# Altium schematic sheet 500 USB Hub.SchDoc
size A3; Organization: Toradex Solutions Inc.; Address1: 6415 Northwest Drive; Address2: Mississauga, ON, L4V 1X1; Address3: Canada
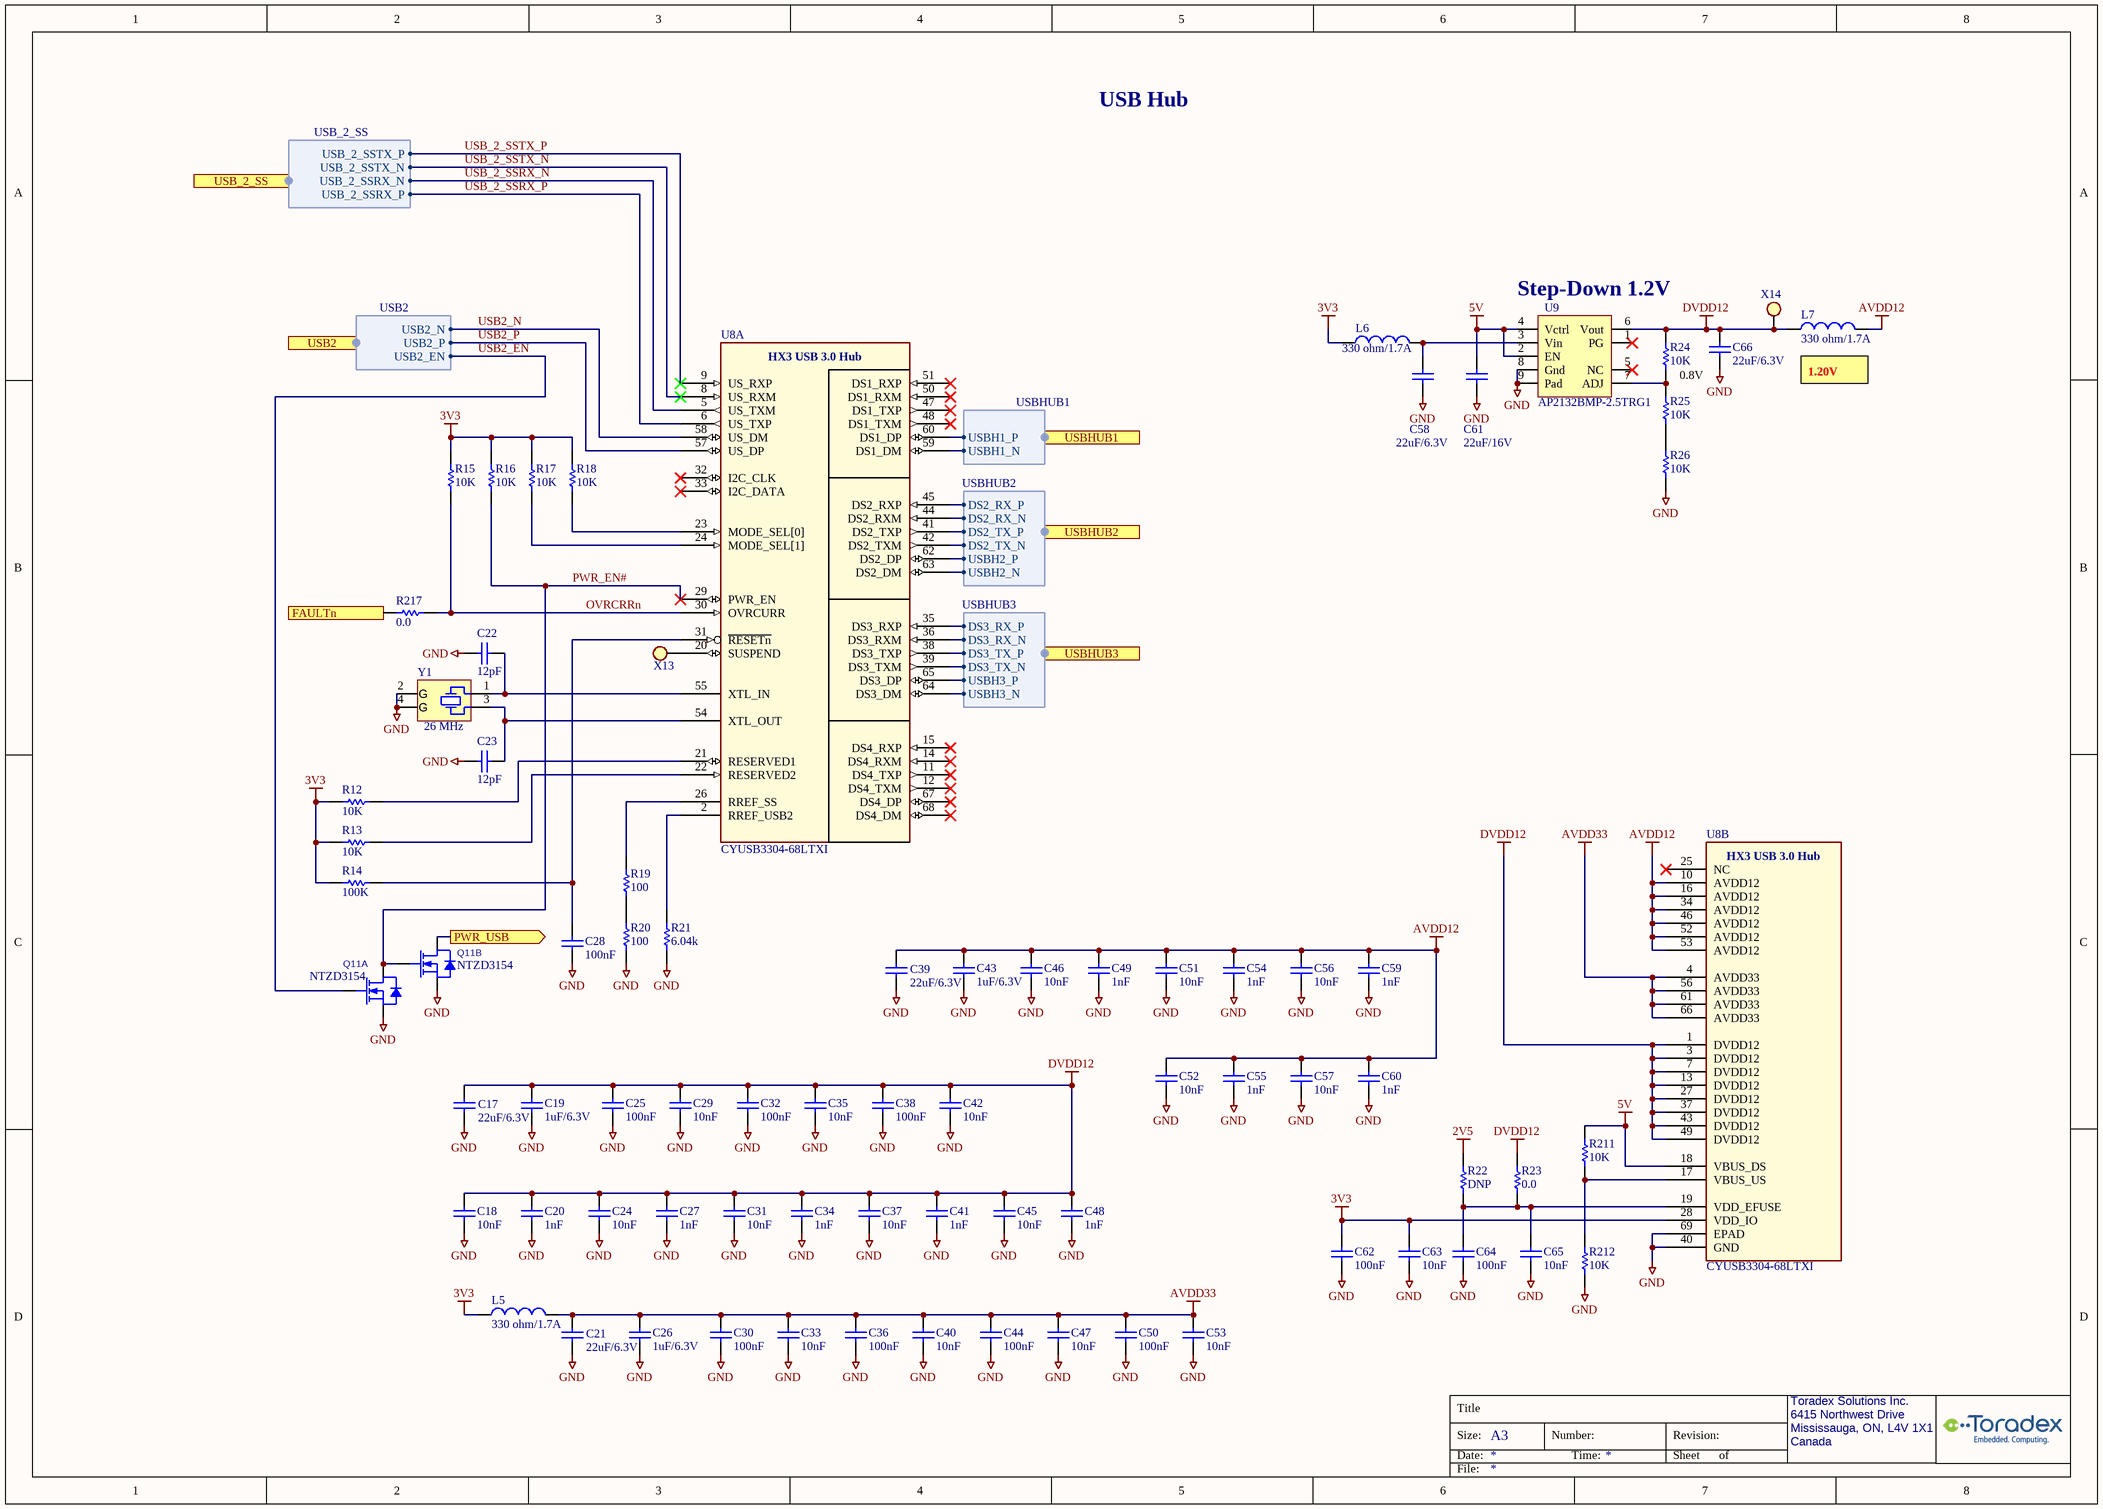
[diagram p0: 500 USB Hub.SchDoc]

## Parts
C17  22uF/6.3V  [C0402_CAPC1005L]
C18  10nF  [C0402_CAPC1005L]
C19  value 1uF/6.3V  [C0402_CAPC1005L]  (hidden comment: 1006-Cap-0402-1uF/6V3)
C20  value 1nF  [C0402_CAPC1005L]  (hidden comment: 0318-Cap-0402-1nF/50V)
C21  22uF/6.3V  [C0402_CAPC1005L]
C22  value 12pF  [C0402_CAPC1005L]  (hidden comment: 0319-Cap-0402-12pF/50V)
C23  value 12pF  [C0402_CAPC1005L]  (hidden comment: 0319-Cap-0402-12pF/50V)
C24  10nF  [C0402_CAPC1005L]
C25  100nF  [C0402_CAPC1005L]
C26  value 1uF/6.3V  [C0402_CAPC1005L]  (hidden comment: 1006-Cap-0402-1uF/6V3)
C27  value 1nF  [C0402_CAPC1005L]  (hidden comment: 0318-Cap-0402-1nF/50V)
C28  100nF  [C0402_CAPC1005L]
C29  10nF  [C0402_CAPC1005L]
C30  100nF  [C0402_CAPC1005L]
C31  10nF  [C0402_CAPC1005L]
C32  100nF  [C0402_CAPC1005L]
C33  10nF  [C0402_CAPC1005L]
C34  value 1nF  [C0402_CAPC1005L]  (hidden comment: 0318-Cap-0402-1nF/50V)
C35  10nF  [C0402_CAPC1005L]
C36  100nF  [C0402_CAPC1005L]
C37  10nF  [C0402_CAPC1005L]
C38  100nF  [C0402_CAPC1005L]
C39  22uF/6.3V  [C0402_CAPC1005L]
C40  10nF  [C0402_CAPC1005L]
C41  value 1nF  [C0402_CAPC1005L]  (hidden comment: 0318-Cap-0402-1nF/50V)
C42  10nF  [C0402_CAPC1005L]
C43  value 1uF/6.3V  [C0402_CAPC1005L]  (hidden comment: 1006-Cap-0402-1uF/6V3)
C44  100nF  [C0402_CAPC1005L]
C45  10nF  [C0402_CAPC1005L]
C46  10nF  [C0402_CAPC1005L]
C47  10nF  [C0402_CAPC1005L]
C48  value 1nF  [C0402_CAPC1005L]  (hidden comment: 0318-Cap-0402-1nF/50V)
C49  value 1nF  [C0402_CAPC1005L]  (hidden comment: 0318-Cap-0402-1nF/50V)
C50  100nF  [C0402_CAPC1005L]
C51  10nF  [C0402_CAPC1005L]
C52  10nF  [C0402_CAPC1005L]
C53  10nF  [C0402_CAPC1005L]
C54  value 1nF  [C0402_CAPC1005L]  (hidden comment: 0318-Cap-0402-1nF/50V)
C55  value 1nF  [C0402_CAPC1005L]  (hidden comment: 0318-Cap-0402-1nF/50V)
C56  10nF  [C0402_CAPC1005L]
C57  10nF  [C0402_CAPC1005L]
C58  22uF/6.3V  [C0402_CAPC1005L]
C59  value 1nF  [C0402_CAPC1005L]  (hidden comment: 0318-Cap-0402-1nF/50V)
C60  value 1nF  [C0402_CAPC1005L]  (hidden comment: 0318-Cap-0402-1nF/50V)
C61  value 22uF/16V  [C/0805]  (hidden comment: 1314-Cap-0805-22uF/16V)
C62  100nF  [C0402_CAPC1005L]
C63  10nF  [C0402_CAPC1005L]
C64  100nF  [C0402_CAPC1005L]
C65  10nF  [C0402_CAPC1005L]
C66  22uF/6.3V  [C0402_CAPC1005L]
L5  value 330 ohm/1.7A  [INDC1608x095]  (hidden comment: 0405-Fer-0603-330ohm/1.7A)
L6  value 330 ohm/1.7A  [INDC1608x095]  (hidden comment: 0405-Fer-0603-330ohm/1.7A)
L7  value 330 ohm/1.7A  [INDC1608x095]  (hidden comment: 0405-Fer-0603-330ohm/1.7A)
Q11  NTZD3154  [SOT563]  (parts A,B of 2)
R12  value 10K  [R0402_RESC1005L]  (hidden comment: 1572-Res-0402-10K)
R13  value 10K  [R0402_RESC1005L]  (hidden comment: 1572-Res-0402-10K)
R14  value 100K  [R0402_RESC1005L]  (hidden comment: 1977-Res-0402-100K)
R15  value 10K  [R0402_RESC1005L]  (hidden comment: 1572-Res-0402-10K)
R16  value 10K  [R0402_RESC1005L]  (hidden comment: 1572-Res-0402-10K)
R17  value 10K  [R0402_RESC1005L]  (hidden comment: 1572-Res-0402-10K)
R18  value 10K  [R0402_RESC1005L]  (hidden comment: 1572-Res-0402-10K)
R19  value 100  [R/0603]  (hidden comment: 1973-Res-0603-100ohm)
R20  value 100  [R/0603]  (hidden comment: 1973-Res-0603-100ohm)
R21  value 6.04k  [R0402_RESC1005L]  (hidden comment: 2075-Res-0402-6.04K)
R22  value DNP  [R/0603]  (hidden comment: 0000-Res-0603-DNP)
R23  value 0.0  [R/0603]  (hidden comment: 0195-Res-0603-0.0ohm)
R24  value 10K  [R0402_RESC1005L]  (hidden comment: 1572-Res-0402-10K)
R25  value 10K  [R0402_RESC1005L]  (hidden comment: 1572-Res-0402-10K)
R26  value 10K  [R0402_RESC1005L]  (hidden comment: 1572-Res-0402-10K)
R211  value 10K  [R0402_RESC1005L]  (hidden comment: 1572-Res-0402-10K)
R212  value 10K  [R0402_RESC1005L]  (hidden comment: 1572-Res-0402-10K)
R217  value 0.0  [R/0603]  (hidden comment: 0195-Res-0603-0.0ohm)
U8  CYUSB3304-68LTXI  [QFN68_LT68B_CYP]  (parts A,B of 2)
U9  AP2132BMP-2.5TRG1  [SOP-9 TP_ALT]
X13  000-TestPoint2  [TestPoint_3]  (value not drawn)
X14  000-TestPoint2  [TestPoint_3]  (value not drawn)
Y1  value 26 MHz  [OSC_4-SMD_(2.0x1.6)]  (hidden comment: 2097-Xtal 26MHz 2.0x1.6mm)

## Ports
FAULTn (in), PWR_USB (out), USB2 (harness USB2), USB_2_SS (harness USB_2_SS), USBHUB1 (harness USBHUB1), USBHUB2 (harness USBHUB2), USBHUB3 (harness USBHUB3)

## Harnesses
USB2: USB2_N, USB2_P, USB2_EN
USBHUB1: USBH1_N, USBH1_P
USBHUB2: USBH2_N, USBH2_P, DS2_TX_N, DS2_TX_P, DS2_RX_N, DS2_RX_P
USBHUB3: USBH3_N, USBH3_P, DS3_TX_N, DS3_TX_P, DS3_RX_N, DS3_RX_P
USB_2_SS: USB_2_SSTX_N, USB_2_SSTX_P, USB_2_SSRX_N, USB_2_SSRX_P

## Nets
2V5: R22.2
3V3: C62.2 C63.2 L5.1 L6.1 R12.1 R13.1 R14.2 R15.2 R16.2 R17.1 R18.1 U8.28(VDD_IO)
5V: C61.2 R211.2 U8.18(VBUS_DS) U9.2(EN) U9.4(Vctrl)
AVDD12: C39.2 C43.2 C46.2 C49.1 C51.2 C52.2 C54.1 C55.1 C56.2 C57.2 C59.1 C60.1 L7.2 U8.10(AVDD12) U8.16(AVDD12) U8.34(AVDD12) U8.46(AVDD12) U8.52(AVDD12) U8.53(AVDD12)
AVDD33: C21.2 C26.2 C30.2 C33.2 C36.2 C40.2 C44.2 C47.2 C50.2 C53.2 L5.2 U8.4(AVDD33) U8.56(AVDD33) U8.61(AVDD33) U8.66(AVDD33)
DVDD12: C17.2 C18.2 C19.2 C20.1 C24.2 C25.2 C27.1 C29.2 C31.2 C32.2 C34.1 C35.2 C37.2 C38.2 C41.1 C42.2 C45.2 C48.1 C66.2 L7.1 R23.1 R24.2 U8.1(DVDD12) U8.3(DVDD12) U8.7(DVDD12) U8.13(DVDD12) U8.27(DVDD12) U8.37(DVDD12) U8.43(DVDD12) U8.49(DVDD12) U9.6(Vout) X14.1
GND: C17.1 C18.1 C19.1 C20.2 C21.1 C22.1 C23.1 C24.1 C25.1 C26.1 C27.2 C28.1 C29.1 C30.1 C31.1 C32.1 C33.1 C34.2 C35.1 C36.1 C37.1 C38.1 C39.1 C40.1 C41.2 C42.1 C43.1 C44.1 C45.1 C46.1 C47.1 C48.2 C49.2 C50.1 C51.1 C52.1 C53.1 C54.2 C55.2 C56.1 C57.1 C58.1 C59.2 C60.2 C61.1 C62.1 C63.1 C64.1 C65.1 C66.1 Q11.1(S) Q11.4(S) R20.2 R21.2 R26.1 R212.1 U8.40(GND) U8.69(EPAD) U9.8(Gnd) U9.9(Pad) Y1.2(GND) Y1.4(GND)
FAULTn: R217.1 ; port FAULTn
OVRCRRn: R15.1 R217.2 U8.30(OVRCURR)
PWR_EN#: Q11.5(G) Q11.6(D) R16.1 U8.29(PWR_EN)
PWR_USB: Q11.3(D) ; port PWR_USB
USB2_EN: Q11.2(G) ; port USB2.USB2_EN
USB2_N: U8.58(US_DM) ; port USB2.USB2_N
USB2_P: U8.57(US_DP) ; port USB2.USB2_P
USB_2_SSRX_N: U8.5(US_TXM) ; port USB_2_SS.USB_2_SSRX_N
USB_2_SSRX_P: U8.6(US_TXP) ; port USB_2_SS.USB_2_SSRX_P
USB_2_SSTX_N: U8.8(US_RXM) ; port USB_2_SS.USB_2_SSTX_N
USB_2_SSTX_P: U8.9(US_RXP) ; port USB_2_SS.USB_2_SSTX_P
NetC22_2: C22.2 U8.55(XTL_IN) Y1.1
NetC23_2: C23.2 U8.54(XTL_OUT) Y1.3
NetC28_2: C28.2 R14.1 U8.31(~{RESETn})
NetC58_2: C58.2 L6.2 U9.3(Vin)
NetC64_2: C64.2 C65.2 R22.1 R23.2 U8.19(VDD_EFUSE)
NetR12_2: R12.2 U8.21(RESERVED1)
NetR13_2: R13.2 U8.22(RESERVED2)
NetR17_2: R17.2 U8.24(MODE_SEL[1])
NetR18_2: R18.2 U8.23(MODE_SEL[0])
NetR19_1: R19.1 U8.26(RREF_SS)
NetR19_2: R19.2 R20.1
NetR21_1: R21.1 U8.2(RREF_USB2)
NetR24_1: R24.1 R25.2 U9.7(ADJ)
NetR25_1: R25.1 R26.2
NetR211_1: R211.1 R212.2 U8.17(VBUS_US)
NetU8_20: U8.20(SUSPEND) X13.1
NetU8_35: U8.35(DS3_RXP) ; port USBHUB3.DS3_RX_P
NetU8_36: U8.36(DS3_RXM) ; port USBHUB3.DS3_RX_N
NetU8_38: U8.38(DS3_TXP) ; port USBHUB3.DS3_TX_P
NetU8_39: U8.39(DS3_TXM) ; port USBHUB3.DS3_TX_N
NetU8_41: U8.41(DS2_TXP) ; port USBHUB2.DS2_TX_P
NetU8_42: U8.42(DS2_TXM) ; port USBHUB2.DS2_TX_N
NetU8_44: U8.44(DS2_RXM) ; port USBHUB2.DS2_RX_N
NetU8_45: U8.45(DS2_RXP) ; port USBHUB2.DS2_RX_P
NetU8_59: U8.59(DS1_DM) ; port USBHUB1.USBH1_N
NetU8_60: U8.60(DS1_DP) ; port USBHUB1.USBH1_P
NetU8_62: U8.62(DS2_DP) ; port USBHUB2.USBH2_P
NetU8_63: U8.63(DS2_DM) ; port USBHUB2.USBH2_N
NetU8_64: U8.64(DS3_DM) ; port USBHUB3.USBH3_N
NetU8_65: U8.65(DS3_DP) ; port USBHUB3.USBH3_P

Not connected (* = marked no-connect by the designer): U8 11(DS4_TXP)* 12(DS4_TXM)* 14(DS4_RXM)* 15(DS4_RXP)* 25(NC)* 32(I2C_CLK)* 33(I2C_DATA)* 47(DS1_TXP)* 48(DS1_TXM)* 50(DS1_RXM)* 51(DS1_RXP)* 67(DS4_DP)* 68(DS4_DM)*; U9 1(PG)* 5(NC)*

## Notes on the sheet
- USB Hub
- Step-Down 1.2V
- 0.8V
- (near L7) 1.20V

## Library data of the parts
C17 C21 C39 = 2404-Cap-0402-22uF/6.3V: (-55 to 85 DegC) CAP CER 22UF 6.3V 20% X5R 0402; Mfr: Murata; MfrNo: GRM155R60J226ME11D; PN: 2404
C18 C24 C29 C31 C33 C35 C37 C40 C42 C45-C47 C51-C53 C56 C57 C63 C65 = 1149-Cap-0402-10nF/50V: Cap Ceramic 10nF 50V X7R 10% 0402; Mfr: Yageo; MfrNo: CC0402KRX7R9BB103; Alt: CL05B103KB5NNNC,UMK105BJ103KV-F,CL05B103KB5NFNC,0402B103K500CT,CC0402KRX7R9BB103; PN: 1149
C19 C26 C43 = 1006-Cap-0402-1uF/6V3: Cap Ceramic 1uF 6.3V X5R 20% SMD 0402 85C T/R; Mfr: Samsung; MfrNo: CL05A105MQ5NNNC; Alt: CL05A105MP5NNNC,CL05A105KQ5NNNC,CL05A105KP5NNNC,CL05A105JQ5NNNC; PN: 1006; Desc: Cap Ceramic 1uF 6.3V X5R 20% SMD 0402 85C Paper T/R
C20 C27 C34 C41 C48 C49 C54 C55 C59 C60 = 0318-Cap-0402-1nF/50V: CAP CER 1000PF 50V 5% NP0 0402; Mfr: Samsung Electro-Mechanics America, Inc; MfrNo: CL05C102JB5NNNC; Alt: 399-10034-1-ND; PN: 318; Alt2: 490-3244-1-ND
C22 C23 = 0319-Cap-0402-12pF/50V: CAP CER 12PF 50V 5% NP0 0402; MfrNo: CL05C120JB5NNNC; Mfr: Samsung Electro-Mechanics America, Inc; PN: 319; Alt: 311-1016-1-ND; Alt2: 490-5924-1-ND
C25 C30 C32 C36 C38 C44 C50 = 1566-Cap-0402-100nF/50V: (-55 to 125 DegC AEC) Cap Ceramic 0.1uF 50V X7R 10% 0402; Mfr: Murata; MfrNo: GRT155R71H104KE01D; Alt: CL05B104KB54PNC,GCM155R71H104ME02D,GCM155R71H104KE02D,GCM155R71H104KE02J; PN: 1566
C28 = 1566-Cap-0402-100nF/50V: (-55 to 125 DegC AEC) Cap Ceramic 0.1uF 50V X7R 10% 0402; MfrNo: GRT155R71H104KE01D; Mfr: Murata; Alt: CL05B104KB54PNC,GCM155R71H104ME02D,GCM155R71H104KE02D,GCM155R71H104KE02J; PN: 1566
C58 C66 = 2404-Cap-0402-22uF/6.3V: (-55 to 85 DegC) CAP CER 22UF 6.3V 20% X5R 0402; MfrNo: GRM155R60J226ME11D; Mfr: Murata; PN: 2404
C61 = 1314-Cap-0805-22uF/16V: (-55 to 85 DegC) CAP CER 22uF 16V X5R 0805; MfrNo: CL21A226MOQNNNE; Mfr: Samsung; PN: 1314; Alt: CL21A226MOCLRNC,CL21A226KOQNNNG,GRM21BR61C226ME44L,EMK212BBJ226MG-T
C62 C64 = 1566-Cap-0402-100nF/50V: (-55 to 125 DegC AEC) Cap Ceramic 0.1uF 50V X7R 10% 0402; Mfr: Murata; MfrNo: GRT155R71H104KE01D; PN: 1566; Alt: CL05B104KB54PNC,GCM155R71H104ME02D,GCM155R71H104KE02D,GCM155R71H104KE02J
L5-L7 = 0405-Fer-0603-330ohm/1.7A: (-55 to 125 DegC) FERRITE BEAD 330 OHM 0603 1.7A 80mohm, typ 48mohm; Mfr: TDK Corporation; MfrNo: MPZ1608S331ATA00; PN: 405; TR: 445-5221-2-ND; DR: 445-5221-6-ND; DR2: 810-MPZ1608S331ATA00
Q11 = 1146-NTZD3154NT1G: (-55 to 150 DegC) MOSFET 2N-CH (dual) 20V 0.54A SOT-563 1.6x1.6mm Vth:1V Ron typ:400m@4.5V, 500m@2.5V, 700m@1.8V; Mfr: ON Semiconductor; PN: 1146; Alt: NTZD3154NT5G,PMDT290UNE,115
R12 R13 R15-R18 R211 R212 = 1572-Res-0402-10K: (-55 to 155 DegC AEC) RES 10K OHM 1% 1/16W 100ppm 0402; Mfr: Stackpole Electronics; MfrNo: RMCF0402FT10K0; PN: 1572; Alt: AC0402FR-0710KL,AC0402FR-1310KL,CRGCQ0402F10K
R14 = 1977-Res-0402-100K: (-55 to 155 DegC) RES 100K OHM 1/16W 1% 0402 SMD; Mfr: Yageo; MfrNo: RC0402FR-07100KL; PN: 1977
R19 R20 = 1973-Res-0603-100ohm: (-55 to 155 DegC) RES 100 OHM 1/10W 1% 0603; Mfr: Yageo; MfrNo: RC0603FR-07100RL; PN: 1973
R21 = 2075-Res-0402-6.04K: (-55 to 155 DegC) RES 6.04K OHM 1/10W 1% 0402 SMD; Mfr: Panasonic; MfrNo: ERJ-2RKF6041X; PN: 2075
R22 = 0000-Res-0603-DNP: RES 0603
R23 = 0195-Res-0603-0.0ohm: RES 0.0 OHM 1/10W JUMP 0603; Mfr: Samsung; MfrNo: RC1608J000CS; Alt: 311-0.0GRCT-ND; PN: 195; Alt2: A106051CT-ND; TR: 1276-3510-2-ND
R24-R26 = 1572-Res-0402-10K: (-55 to 155 DegC AEC) RES 10K OHM 1% 1/16W 100ppm 0402; MfrNo: RMCF0402FT10K0; Mfr: Stackpole Electronics; Alt: AC0402FR-0710KL,AC0402FR-1310KL,CRGCQ0402F10K; PN: 1572
R217 = 0195-Res-0603-0.0ohm: RES 0.0 OHM 1/10W JUMP 0603; Mfr: Samsung; MfrNo: RC1608J000CS; PN: 195; Alt: 311-0.0GRCT-ND; Alt2: A106051CT-ND; TR: 1276-3510-2-ND
U8 = 2096-CYUSB3304-68LTXI: (-40 to 85 DegC) IC USB 3.0 HUB 4-PORT 68QFN; Mfr: Infineon Technologies; PN: 2096
U9 = 1467-AP2132BMP-2.5: (-40 to 85 DegC) IC REG LDO LINEAR POS ADJ 5V 2A 8SO; Mfr: Diodes; PN: 1467; Desc: (-40 to 85 DegC) IC REG BUCK ADJ Sync 5A Vin:3.8 to 40V 100-2200kHz FSS (spread spectrum) MaxDuty:100% SO-8EP; Note: These can be also used with adjust Voltage circuit: AP2132BMP-1.2TRG1, AP2132BMP-1.5TRG1
X13 X14 = 000-TestPoint2: TestPoint SMD; Note: PCB footprint only, no parts to buy or assemble
Y1 = 2097-Xtal 26MHz 2.0x1.6mm: (-40 to 85 DegC) XTAL CRYSTAL 26.0000MHZ 12PF SMD +-15ppm +-10ppm 2.0x1.6mm; MfrNo: XRCGB26M000F1SADR0; Mfr: Murata Electronics; PN: 2097; Desc: (-20 to 70 DegC) XTAL CRYSTAL 26.0000MHZ 12PF SMD +-10ppm +-10ppm 3.2x2.5mm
